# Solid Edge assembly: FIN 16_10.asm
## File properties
Title: Zylinder
Author: bmolnar
Template: iso assembly.asm
Last saved by: bmolnar
Revision: 8
Application: Solid Edge
Username: bmolnar
Dokumentum tartalom típus: 1
Document Number: FIN 16/10
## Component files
Kolbenstange.par
Profilrohr.par
Kit_1.par
Kit_2.par
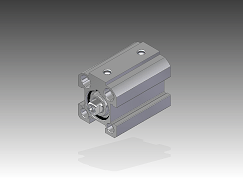
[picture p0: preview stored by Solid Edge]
